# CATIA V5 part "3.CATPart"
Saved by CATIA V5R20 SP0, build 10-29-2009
Part number: 3
Bounding box of the stored display mesh (mm): x -34.998 to 34.998, y -34.998 to 34.998, z -35 to 35
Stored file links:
  E:\Ehsan\Amoozesh\CATIA\CATIA Course\Advanced\Videos\Session-22\3.CATPart
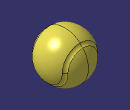
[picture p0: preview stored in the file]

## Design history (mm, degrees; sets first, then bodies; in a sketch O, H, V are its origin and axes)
AxisSystem1: origin (0, 0, 0), X (1, 0, 0), Y (0, 1, 0), Z (0, 0, 1)
Set1
  Sphere1: Center vertex [YZ plane of AxisSystem1 | ZX plane of AxisSystem1 | XY plane of AxisSystem1], Axis AxisSystem1, Radius 35, Angle1 -90, Angle3 90, Angle4 270
  Sketch1 on YZ plane of AxisSystem1, origin (0, 0, 0), H (0, 1, 0), V (0, 0, 1)
    construction line L1 (0, 0) -> (0, 42.8941)
    line L2 (-26, 0) -> (-26, 42.8941)
    line L3 (26, 42.8941) -> (26, 0)
    arc A1 centre (0, 0) radius 26 from (26, 0) to (-26, 0) cw
    circle A2 centre (28.2843, 28.2843) radius 6
    construction line L4 (0, 0) -> (28.2843, 28.2843)
    distance L1 L2 = 26
    length L4 = 40
    angle L4 H = 45
    radius A2 = 6
    vertical: L1 V
    tangency: A1 L2, A1 L3
  Project1: ToProject Sketch1, Support Sphere1, Direction YZ plane of AxisSystem1
  CloseSurface1: CloseElement Sphere1
  Sweep1: type Unspec, Profile sketch element, Guide Project1
  Remove1: tool Sweep1
  Symmetry1: ToTransfor Remove1, Reference YZ plane of AxisSystem1
  Add1: tool Symmetry1
Body1 (main body)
